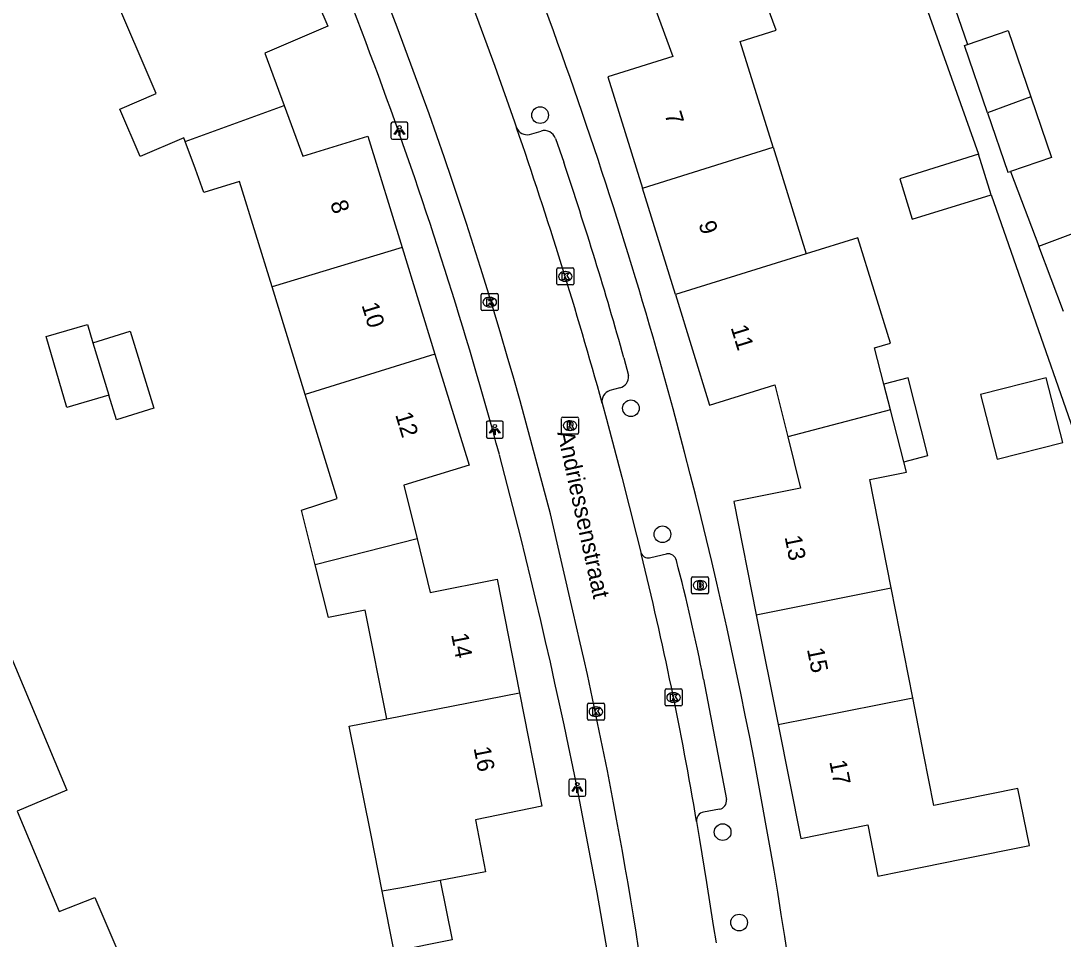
# Model space of a CAD drawing. Extents: x 159053 to 160041, y 380450 to 381422.
# Drawn here: x 159447 to 159508.2, y 380903.9 to 380957.8 of the extents above; entities that cross this region are included whole.
import ezdxf

# ---------------------------------------------------------------- set-up
doc = ezdxf.new("R2010")
doc.units = 0
for name, color, linetype in [('IMGEO_Boom', 7, 'Continuous'), ('IMGEO_Brandkraan', 7, 'Continuous'), ('IMGEO_Kolk', 7, 'Continuous'), ('IMGEO_Lichtpunt', 7, 'Continuous'), ('IMGEO_Openbare_ruimte_label', 7, 'Continuous'), ('IMGEO_Pand', 7, 'Continuous'), ('IMGEO_Pand_nummerreeks', 7, 'Continuous'), ('IMGEO_Rijbaan_lokaal_open', 7, 'Continuous'), ('IMGEO_Rioolput', 7, 'Continuous'), ('IMGEO_Voetpad_open', 7, 'Continuous')]:
    doc.layers.add(name, color=color, linetype=linetype)

msp = doc.modelspace()

# ---------------------------------------------------------------- linework, layer by layer
at = {"layer": 'IMGEO_Boom'}
for centre in [(159477.48, 380952.251), (159482.811, 380935.05), (159484.658, 380927.655), (159488.191, 380910.182), (159489.157, 380904.873)]:
    msp.add_circle(centre, 0.489, dxfattribs=at)
at = {"layer": 'IMGEO_Brandkraan'}
for p, q in [((159486.36, 380924.236), (159486.36, 380925.088)), ((159486.435, 380925.162), (159487.287, 380925.162)), ((159486.848, 380924.942), (159486.873, 380924.942)), ((159487.361, 380925.088), (159487.361, 380924.236)), ((159487.287, 380924.162), (159486.435, 380924.162)), ((159486.871, 380924.382), (159486.846, 380924.382))]:
    msp.add_line(p, q, dxfattribs=at)
for points in [[(159486.36, 380924.236), (159486.36, 380925.088)], [(159486.435, 380925.162), (159487.287, 380925.162)], [(159486.708, 380924.862), (159486.708, 380924.462), (159486.921, 380924.462)], [(159486.939, 380924.862), (159486.708, 380924.862)], [(159486.887, 380924.781), (159486.833, 380924.781), (159486.833, 380924.705)], [(159486.833, 380924.705), (159486.886, 380924.705)], [(159486.895, 380924.629), (159486.833, 380924.629), (159486.833, 380924.548)], [(159487.361, 380925.088), (159487.361, 380924.236)], [(159487.287, 380924.162), (159486.435, 380924.162)], [(159486.833, 380924.548), (159486.895, 380924.548)]]:
    msp.add_lwpolyline(points, dxfattribs=at)
for centre, radius, start, end in [((159486.437, 380925.086), 0.0765, 91.55205, 178.44795), ((159486.437, 380925.086), 0.0765, 91.55205, 178.44795), ((159486.888, 380924.743), 0.0379, 267.82845, 90.93552), ((159486.896, 380924.588), 0.0404, 269.87594, 90.50774), ((159486.943, 380924.717), 0.145, 59.4692, 91.53667), ((159486.968, 380924.764), 0.0922, 285.51372, 58.15012), ((159486.973, 380924.572), 0.105, 301.31148, 78.98903), ((159487.285, 380925.086), 0.0765, 1.55205, 88.44795), ((159487.285, 380925.086), 0.0765, 1.55205, 88.44795), ((159486.437, 380924.238), 0.0765, 181.55205, 268.44795), ((159486.437, 380924.238), 0.0765, 181.55205, 268.44795), ((159486.927, 380924.713), 0.251, 268.66757, 293.53466), ((159487.285, 380924.238), 0.0765, 271.55205, 358.44795), ((159487.285, 380924.238), 0.0765, 271.55205, 358.44795)]:
    msp.add_arc(centre, radius, start, end, dxfattribs=at)
for centre, major_axis, ratio, start_param, end_param in [((159486.847, 380924.662), (-0.387, 0.002), 0.722429, 4.712389, 7.853982), ((159486.872, 380924.662), (-0.39, 0.002), 0.717154, 1.570796, 4.712389)]:
    msp.add_ellipse(centre, major_axis=major_axis, ratio=ratio, start_param=start_param, end_param=end_param, dxfattribs=at)
at = {"layer": 'IMGEO_Kolk'}
for p, q in [((159478.457, 380942.362), (159478.457, 380943.214)), ((159478.532, 380943.288), (159479.384, 380943.288)), ((159478.945, 380943.068), (159478.97, 380943.068)), ((159479.458, 380943.214), (159479.458, 380942.362)), ((159478.968, 380942.508), (159478.943, 380942.508)), ((159474.099, 380941.78), (159474.951, 380941.78)), ((159479.384, 380942.288), (159478.532, 380942.288)), ((159474.024, 380940.854), (159474.024, 380941.706)), ((159474.512, 380941.56), (159474.537, 380941.56)), ((159475.025, 380941.706), (159475.025, 380940.854)), ((159474.951, 380940.78), (159474.099, 380940.78)), ((159474.535, 380941), (159474.51, 380941)), ((159484.81, 380917.657), (159484.81, 380918.509)), ((159484.885, 380918.583), (159485.737, 380918.583)), ((159485.811, 380918.509), (159485.811, 380917.657)), ((159485.298, 380918.363), (159485.323, 380918.363)), ((159480.252, 380916.821), (159480.252, 380917.673)), ((159480.327, 380917.747), (159481.179, 380917.747)), ((159480.74, 380917.527), (159480.765, 380917.527)), ((159481.253, 380917.673), (159481.253, 380916.821)), ((159485.737, 380917.583), (159484.885, 380917.583)), ((159485.321, 380917.803), (159485.296, 380917.803)), ((159481.179, 380916.747), (159480.327, 380916.747)), ((159480.763, 380916.967), (159480.738, 380916.967))]:
    msp.add_line(p, q, dxfattribs=at)
for points in [[(159478.457, 380942.362), (159478.457, 380943.214)], [(159478.532, 380943.288), (159479.384, 380943.288)], [(159478.778, 380942.988), (159478.901, 380942.988), (159478.901, 380942.837), (159479.031, 380942.988), (159479.195, 380942.988), (159479.049, 380942.837), (159479.202, 380942.588), (159479.05, 380942.588), (159478.965, 380942.752), (159478.901, 380942.685), (159478.901, 380942.588), (159478.778, 380942.588), (159478.778, 380942.988)], [(159479.458, 380943.214), (159479.458, 380942.362)], [(159474.099, 380941.78), (159474.951, 380941.78)], [(159479.384, 380942.288), (159478.532, 380942.288)], [(159474.024, 380940.854), (159474.024, 380941.706)], [(159474.345, 380941.48), (159474.468, 380941.48), (159474.468, 380941.329), (159474.598, 380941.48), (159474.762, 380941.48), (159474.616, 380941.329), (159474.769, 380941.08), (159474.617, 380941.08), (159474.532, 380941.244), (159474.468, 380941.177), (159474.468, 380941.08), (159474.345, 380941.08), (159474.345, 380941.48)], [(159475.025, 380941.706), (159475.025, 380940.854)], [(159474.951, 380940.78), (159474.099, 380940.78)], [(159484.81, 380917.657), (159484.81, 380918.509)], [(159484.885, 380918.583), (159485.737, 380918.583)], [(159485.811, 380918.509), (159485.811, 380917.657)], [(159485.131, 380918.283), (159485.254, 380918.283), (159485.254, 380918.132), (159485.384, 380918.283), (159485.548, 380918.283), (159485.402, 380918.132), (159485.555, 380917.883), (159485.403, 380917.883), (159485.318, 380918.047), (159485.254, 380917.98), (159485.254, 380917.883), (159485.131, 380917.883), (159485.131, 380918.283)], [(159480.252, 380916.821), (159480.252, 380917.673)], [(159480.327, 380917.747), (159481.179, 380917.747)], [(159480.573, 380917.447), (159480.696, 380917.447), (159480.696, 380917.296), (159480.826, 380917.447), (159480.99, 380917.447), (159480.844, 380917.296), (159480.997, 380917.047), (159480.845, 380917.047), (159480.76, 380917.211), (159480.696, 380917.144), (159480.696, 380917.047), (159480.573, 380917.047), (159480.573, 380917.447)], [(159481.253, 380917.673), (159481.253, 380916.821)], [(159485.737, 380917.583), (159484.885, 380917.583)], [(159481.179, 380916.747), (159480.327, 380916.747)]]:
    msp.add_lwpolyline(points, dxfattribs=at)
for centre, start, end in [((159478.534, 380943.212), 91.55205, 178.44795), ((159478.534, 380943.212), 91.55205, 178.44795), ((159479.382, 380943.212), 1.55205, 88.44795), ((159479.382, 380943.212), 1.55205, 88.44795), ((159478.534, 380942.364), 181.55205, 268.44795), ((159478.534, 380942.364), 181.55205, 268.44795), ((159479.382, 380942.364), 271.55205, 358.44795), ((159479.382, 380942.364), 271.55205, 358.44795), ((159474.101, 380941.704), 91.55205, 178.44795), ((159474.101, 380941.704), 91.55205, 178.44795), ((159474.949, 380941.704), 1.55205, 88.44795), ((159474.949, 380941.704), 1.55205, 88.44795), ((159474.101, 380940.856), 181.55205, 268.44795), ((159474.101, 380940.856), 181.55205, 268.44795), ((159474.949, 380940.856), 271.55205, 358.44795), ((159474.949, 380940.856), 271.55205, 358.44795), ((159484.887, 380918.507), 91.55205, 178.44795), ((159484.887, 380918.507), 91.55205, 178.44795), ((159485.735, 380918.507), 1.55205, 88.44795), ((159485.735, 380918.507), 1.55205, 88.44795), ((159480.329, 380917.671), 91.55205, 178.44795), ((159480.329, 380917.671), 91.55205, 178.44795), ((159481.177, 380917.671), 1.55205, 88.44795), ((159481.177, 380917.671), 1.55205, 88.44795), ((159484.887, 380917.659), 181.55205, 268.44795), ((159484.887, 380917.659), 181.55205, 268.44795), ((159485.735, 380917.659), 271.55205, 358.44795), ((159485.735, 380917.659), 271.55205, 358.44795), ((159480.329, 380916.823), 181.55205, 268.44795), ((159480.329, 380916.823), 181.55205, 268.44795), ((159481.177, 380916.823), 271.55205, 358.44795), ((159481.177, 380916.823), 271.55205, 358.44795)]:
    msp.add_arc(centre, 0.0765, start, end, dxfattribs=at)
for centre, major_axis, ratio, start_param, end_param in [((159478.944, 380942.788), (-0.387, 0.002), 0.722429, 4.712389, 7.853982), ((159478.969, 380942.788), (-0.39, 0.002), 0.717154, 1.570796, 4.712389), ((159474.511, 380941.28), (-0.387, 0.002), 0.722429, 4.712389, 7.853982), ((159474.536, 380941.28), (-0.39, 0.002), 0.717154, 1.570796, 4.712389), ((159485.297, 380918.083), (-0.387, 0.002), 0.722429, 4.712389, 7.853982), ((159485.322, 380918.083), (-0.39, 0.002), 0.717154, 1.570796, 4.712389), ((159480.739, 380917.247), (-0.387, 0.002), 0.722429, 4.712389, 7.853982), ((159480.764, 380917.247), (-0.39, 0.002), 0.717154, 1.570796, 4.712389)]:
    msp.add_ellipse(centre, major_axis=major_axis, ratio=ratio, start_param=start_param, end_param=end_param, dxfattribs=at)
at = {"layer": 'IMGEO_Lichtpunt'}
for p, q in [((159468.732, 380951.738), (159468.732, 380950.931)), ((159468.732, 380951.738), (159468.732, 380950.931)), ((159469.634, 380951.833), (159468.826, 380951.833)), ((159469.634, 380951.833), (159468.826, 380951.833)), ((159469.728, 380950.931), (159469.728, 380951.738)), ((159469.728, 380950.931), (159469.728, 380951.738)), ((159468.826, 380950.837), (159469.634, 380950.837)), ((159468.826, 380950.837), (159469.634, 380950.837)), ((159474.326, 380934.208), (159474.326, 380933.401)), ((159474.326, 380934.208), (159474.326, 380933.401)), ((159475.228, 380934.303), (159474.42, 380934.303)), ((159475.228, 380934.303), (159474.42, 380934.303)), ((159475.322, 380933.401), (159475.322, 380934.208)), ((159475.322, 380933.401), (159475.322, 380934.208)), ((159474.42, 380933.307), (159475.228, 380933.307)), ((159474.42, 380933.307), (159475.228, 380933.307)), ((159479.165, 380913.192), (159479.165, 380912.385)), ((159479.165, 380913.192), (159479.165, 380912.385)), ((159480.067, 380913.287), (159479.259, 380913.287)), ((159480.067, 380913.287), (159479.259, 380913.287)), ((159480.161, 380912.385), (159480.161, 380913.192)), ((159480.161, 380912.385), (159480.161, 380913.192)), ((159479.259, 380912.291), (159480.067, 380912.291)), ((159479.259, 380912.291), (159480.067, 380912.291))]:
    msp.add_line(p, q, dxfattribs=at)
for points in [[(159469.106, 380951.402), (159469.145, 380951.374), (159468.957, 380951.112), (159468.919, 380951.139), (159469.106, 380951.402)], [(159469.208, 380951.354), (159469.255, 380951.354), (159469.255, 380951.032), (159469.208, 380951.032), (159469.208, 380951.354)], [(159469.318, 380951.374), (159469.356, 380951.401), (159469.543, 380951.139), (159469.504, 380951.111), (159469.318, 380951.374)], [(159474.7, 380933.872), (159474.739, 380933.844), (159474.551, 380933.582), (159474.513, 380933.609), (159474.7, 380933.872)], [(159474.802, 380933.824), (159474.849, 380933.824), (159474.849, 380933.502), (159474.802, 380933.502), (159474.802, 380933.824)], [(159474.912, 380933.844), (159474.95, 380933.871), (159475.137, 380933.609), (159475.098, 380933.581), (159474.912, 380933.844)], [(159479.539, 380912.856), (159479.578, 380912.828), (159479.39, 380912.566), (159479.352, 380912.593), (159479.539, 380912.856)], [(159479.641, 380912.808), (159479.688, 380912.808), (159479.688, 380912.486), (159479.641, 380912.486), (159479.641, 380912.808)], [(159479.751, 380912.828), (159479.789, 380912.855), (159479.976, 380912.593), (159479.937, 380912.565), (159479.751, 380912.828)]]:
    msp.add_lwpolyline(points, dxfattribs=at)
for centre in [(159469.231, 380951.536), (159474.825, 380934.006), (159479.664, 380912.99)]:
    msp.add_circle(centre, 0.0994, dxfattribs=at)
for centre, start, end in [((159468.826, 380951.738), 90, 180), ((159468.826, 380951.738), 90, 180), ((159469.634, 380951.738), 0, 90), ((159469.634, 380951.738), 0, 90), ((159468.826, 380950.931), 180, 270), ((159468.826, 380950.931), 180, 270), ((159469.634, 380950.931), 270, 0), ((159469.634, 380950.931), 270, 360), ((159474.42, 380934.208), 90, 180), ((159474.42, 380934.208), 90, 180), ((159475.228, 380934.208), 0, 90), ((159475.228, 380934.208), 0, 90), ((159474.42, 380933.401), 180, 270), ((159474.42, 380933.401), 180, 270), ((159475.228, 380933.401), 270, 0), ((159475.228, 380933.401), 270, 360), ((159479.259, 380913.192), 90, 180), ((159479.259, 380913.192), 90, 180), ((159480.067, 380913.192), 0, 90), ((159480.067, 380913.192), 0, 90), ((159479.259, 380912.385), 180, 270), ((159479.259, 380912.385), 180, 270), ((159480.067, 380912.385), 270, 0), ((159480.067, 380912.385), 270, 360)]:
    msp.add_arc(centre, 0.0946, start, end, dxfattribs=at)
at = {"layer": 'IMGEO_Pand'}
for points in [[(159462.352, 380963.709), (159465.017, 380957.468), (159461.339, 380955.898), (159462.466, 380952.823)], [(159491.145, 380950.369), (159489.212, 380956.58), (159491.332, 380957.235), (159490.467, 380959.578), (159490.05, 380960.707)], [(159456.661, 380950.71), (159456.584, 380950.92), (159454.017, 380949.822), (159452.825, 380952.607), (159454.957, 380953.519), (159452.416, 380959.459)], [(159484.213, 380958.564), (159485.276, 380955.689), (159481.455, 380954.505), (159483.479, 380947.971)], [(159502.564, 380956.405), (159504.944, 380957.218), (159506.273, 380953.33)], [(159503.727, 380952.391), (159502.377, 380956.341), (159502.564, 380956.405)], [(159456.661, 380950.71), (159462.466, 380952.823)], [(159462.466, 380952.823), (159463.558, 380949.841), (159467.381, 380951.015), (159469.389, 380944.479)], [(159506.273, 380953.33), (159503.727, 380952.391)], [(159506.273, 380953.33), (159507.488, 380949.775), (159505.079, 380948.952)], [(159503.727, 380952.391), (159504.921, 380948.898), (159505.079, 380948.952)], [(159461.757, 380942.175), (159459.852, 380948.368), (159457.752, 380947.719), (159457.255, 380949.082), (159456.661, 380950.71)], [(159483.479, 380947.971), (159491.145, 380950.369)], [(159491.145, 380950.369), (159493.095, 380944.105)], [(159503.201, 380949.953), (159498.577, 380948.514), (159499.315, 380946.143), (159503.938, 380947.583)], [(159503.938, 380947.583), (159503.201, 380949.953)], [(159485.415, 380941.722), (159483.479, 380947.971)], [(159506.738, 380944.564), (159509.089, 380945.453), (159510.547, 380941.599)], [(159497.646, 380936.47), (159497.101, 380938.592), (159498.042, 380938.868), (159496.126, 380945.045), (159493.095, 380944.105)], [(159469.389, 380944.479), (159461.757, 380942.175)], [(159469.389, 380944.479), (159471.31, 380938.226)], [(159508.188, 380940.729), (159506.738, 380944.564)], [(159493.095, 380944.105), (159485.415, 380941.722)], [(159463.697, 380935.868), (159461.757, 380942.175)], [(159485.415, 380941.722), (159487.423, 380935.239), (159491.244, 380936.423), (159492.008, 380933.375)], [(159452.184, 380935.823), (159449.718, 380935.1), (159448.495, 380939.264), (159450.922, 380939.975), (159451.248, 380938.891)], [(159451.248, 380938.891), (159453.43, 380939.582), (159454.818, 380935.06), (159452.628, 380934.367), (159452.184, 380935.823)], [(159451.248, 380938.891), (159452.184, 380935.823)], [(159471.31, 380938.226), (159463.697, 380935.868)], [(159471.31, 380938.226), (159473.309, 380931.721), (159469.486, 380930.547), (159470.261, 380927.385)], [(159498.817, 380931.909), (159500.237, 380932.273), (159499.066, 380936.835), (159497.646, 380936.47)], [(159508.148, 380933.046), (159507.173, 380936.841), (159503.32, 380935.852), (159504.295, 380932.057), (159508.148, 380933.046)], [(159498.034, 380934.957), (159497.646, 380936.47)], [(159464.292, 380925.866), (159463.488, 380929.066), (159465.579, 380929.752), (159463.697, 380935.868)], [(159498.034, 380934.957), (159492.008, 380933.375)], [(159498.817, 380931.909), (159498.034, 380934.957)], [(159492.008, 380933.375), (159492.762, 380930.369), (159488.838, 380929.588), (159490.164, 380922.924)], [(159498.07, 380924.515), (159496.819, 380930.872), (159498.972, 380931.306), (159498.817, 380931.909)], [(159470.261, 380927.385), (159464.292, 380925.866)], [(159470.261, 380927.385), (159471.031, 380924.242), (159474.954, 380925.019), (159476.275, 380918.352)], [(159468.488, 380916.821), (159467.213, 380923.198), (159465.072, 380922.765), (159464.292, 380925.866)], [(159490.164, 380922.924), (159498.07, 380924.515)], [(159499.34, 380918.065), (159498.07, 380924.515)], [(159490.164, 380922.924), (159491.441, 380916.505)], [(159445.222, 380921.253), (159445.993, 380921.527), (159449.718, 380912.643), (159446.793, 380911.415)], [(159468.488, 380916.821), (159476.275, 380918.352)], [(159476.275, 380918.352), (159477.591, 380911.706), (159473.681, 380910.9), (159474.269, 380907.843), (159471.62, 380907.336)], [(159491.441, 380916.505), (159499.34, 380918.065)], [(159491.441, 380916.505), (159492.772, 380909.815), (159496.703, 380910.605), (159497.301, 380907.587), (159500, 380908.136), (159502.201, 380908.584), (159506.185, 380909.395), (159505.503, 380912.747), (159500.584, 380911.746), (159500, 380914.713), (159499.34, 380918.065)], [(159468.218, 380906.712), (159467.543, 380910.09), (159466.285, 380916.388), (159468.488, 380916.821)], [(159446.793, 380911.415), (159449.265, 380905.517), (159451.363, 380906.349), (159452.697, 380903.191), (159451.578, 380902.697), (159448.411, 380901.353), (159446.975, 380900.743), (159445.736, 380903.567), (159442.047, 380902.022), (159439.379, 380908.299)], [(159471.62, 380907.336), (159472.316, 380903.852), (159468.925, 380903.174), (159468.218, 380906.712)], [(159471.62, 380907.336), (159469.359, 380906.904), (159468.218, 380906.712)]]:
    msp.add_lwpolyline(points, dxfattribs=at)
at = {"layer": 'IMGEO_Rijbaan_lokaal_open'}
for points in [[(159473.256, 380959.354), (159473.55, 380958.575), (159474.827, 380955.127), (159475.977, 380951.861), (159476.1, 380951.506)], [(159481.124, 380935.349), (159481.381, 380934.413), (159482.283, 380931.013), (159483.144, 380927.609), (159483.413, 380926.522)], [(159479.404, 380923.171), (159478.093, 380928.866), (159477.017, 380932.863)], [(159486.665, 380910.805), (159486.841, 380909.753), (159487.238, 380907.231), (159487.643, 380904.696), (159487.807, 380903.688)]]:
    msp.add_lwpolyline(points, dxfattribs=at)
for centre, radius, start, end in [((159233.18, 380867.705), 252.393, 14.9609, 24.8315), ((159223.575, 380864.124), 267.216, 15.45873, 19.0873), ((159264.406, 380873.012), 225.45, 9.6502, 13.72999), ((159216.691, 380861.712), 269.806, 6.63675, 13.16689)]:
    msp.add_arc(centre, radius, start, end, dxfattribs=at)
at = {"layer": 'IMGEO_Rioolput'}
for p, q in [((159478.732, 380933.609), (159478.732, 380934.461)), ((159478.807, 380934.535), (159479.659, 380934.535)), ((159479.733, 380934.461), (159479.733, 380933.609)), ((159479.22, 380934.315), (159479.245, 380934.315)), ((159479.659, 380933.535), (159478.807, 380933.535)), ((159479.243, 380933.755), (159479.218, 380933.755))]:
    msp.add_line(p, q, dxfattribs=at)
for points in [[(159478.732, 380933.609), (159478.732, 380934.461)], [(159478.807, 380934.535), (159479.659, 380934.535)], [(159479.733, 380934.461), (159479.733, 380933.609)], [(159479.321, 380934.233), (159479.069, 380934.235), (159479.069, 380933.835)], [(159479.069, 380933.835), (159479.193, 380933.835), (159479.193, 380933.997), (159479.204, 380933.997)], [(159479.247, 380934.154), (159479.193, 380934.154), (159479.193, 380934.073)], [(159479.193, 380934.073), (159479.245, 380934.073)], [(159479.251, 380933.968), (159479.322, 380933.835), (159479.462, 380933.835), (159479.397, 380933.961)], [(159479.659, 380933.535), (159478.807, 380933.535)]]:
    msp.add_lwpolyline(points, dxfattribs=at)
for centre, radius, start, end in [((159478.809, 380934.459), 0.0765, 91.55205, 178.44795), ((159478.809, 380934.459), 0.0765, 91.55205, 178.44795), ((159479.657, 380934.459), 0.0765, 1.55205, 88.44795), ((159479.657, 380934.459), 0.0765, 1.55205, 88.44795), ((159479.203, 380933.944), 0.0533, 26.02933, 88.69889), ((159479.229, 380934.262), 0.19, 274.7715, 282.96867), ((159479.253, 380934.058), 0.0964, 77.00612, 93.18647), ((159479.267, 380934.115), 0.0378, 276.66336, 79.67722), ((159479.32, 380934.123), 0.109, 350.36119, 89.41601), ((159479.318, 380934.123), 0.112, 277.58423, 350.98172), ((159479.302, 380933.908), 0.108, 29.51342, 73.79051), ((159478.809, 380933.611), 0.0765, 181.55205, 268.44795), ((159478.809, 380933.611), 0.0765, 181.55205, 268.44795), ((159479.657, 380933.611), 0.0765, 271.55205, 358.44795), ((159479.657, 380933.611), 0.0765, 271.55205, 358.44795)]:
    msp.add_arc(centre, radius, start, end, dxfattribs=at)
for centre, major_axis, ratio, start_param, end_param in [((159479.219, 380934.035), (-0.387, 0.002), 0.722429, 4.712389, 7.853982), ((159479.244, 380934.035), (-0.39, 0.002), 0.717154, 1.570796, 4.712389)]:
    msp.add_ellipse(centre, major_axis=major_axis, ratio=ratio, start_param=start_param, end_param=end_param, dxfattribs=at)
at = {"layer": 'IMGEO_Voetpad_open'}
for points in [[(159489.748, 380986.752), (159496.126, 380969.914), (159503.201, 380949.953)], [(159501.828, 380958.487), (159502.564, 380956.405)], [(159476.865, 380951.114), (159477.533, 380951.321)], [(159478.388, 380950.885), (159478.865, 380949.485)], [(159505.079, 380948.952), (159506.738, 380944.564)], [(159503.938, 380947.583), (159511.089, 380927.112)], [(159482.401, 380938.007), (159482.675, 380936.971)], [(159482.156, 380936.244), (159481.566, 380936.087)], [(159483.985, 380926.296), (159484.896, 380926.508)], [(159487.071, 380919.159), (159488.419, 380912.095)], [(159488.001, 380911.523), (159487.073, 380911.353)]]:
    msp.add_lwpolyline(points, dxfattribs=at)
for centre, radius, start, end in [((159218.341, 380862.613), 276.59, 15.17696, 24.81537), ((159219.51, 380862.954), 264.833, 15.18628, 24.98637), ((159476.725, 380951.784), 0.684, 203.95351, 281.78363), ((159477.73, 380950.65), 0.699, 19.62732, 106.33483), ((159251.784, 380873.245), 239.538, 15.68583, 18.55891), ((159481.975, 380936.922), 0.702, 284.93547, 4.019), ((159481.746, 380935.478), 0.635, 106.47508, 191.68879), ((159206.417, 380859.851), 288.822, 6.70726, 15.08666), ((159160.823, 380848.813), 325.18, 7.81295, 14.88202), ((159483.832, 380926.745), 0.475, 208.059, 288.82256), ((159484.974, 380925.995), 0.519, 13.93137, 98.6885), ((159373.205, 380896.764), 116.047, 11.12685, 14.6531), ((159487.905, 380912.032), 0.518, 280.65351, 7.03011), ((159487.151, 380910.869), 0.49, 99.16314, 187.49961)]:
    msp.add_arc(centre, radius, start, end, dxfattribs=at)

# ---------------------------------------------------------------- texts
at = {"layer": 'IMGEO_Openbare_ruimte_label'}
msp.add_text('Andriessenstraat', height=1, rotation=282.29886, dxfattribs=at).set_placement((159478.48, 380933.625))
at = {"layer": 'IMGEO_Pand_nummerreeks'}
for s, rotation, p in [('7', 287.21133, (159484.775, 380952.303)), ('8', 287.07936, (159465.154, 380947.096)), ('9', 287.21133, (159486.764, 380945.881)), ('10', 287.07936, (159466.995, 380941.104)), ('11', 287.21144, (159488.652, 380939.789)), ('12', 287.07936, (159468.969, 380934.679)), ('13', 281.25268, (159491.821, 380927.505)), ('14', 281.20396, (159472.254, 380921.774)), ('15', 281.25252, (159493.132, 380920.914)), ('16', 281.20111, (159473.572, 380915.118)), ('17', 281.25252, (159494.444, 380914.323))]:
    msp.add_text(s, height=1, rotation=rotation, dxfattribs=at).set_placement(p)

doc.saveas('drawing.dxf')
